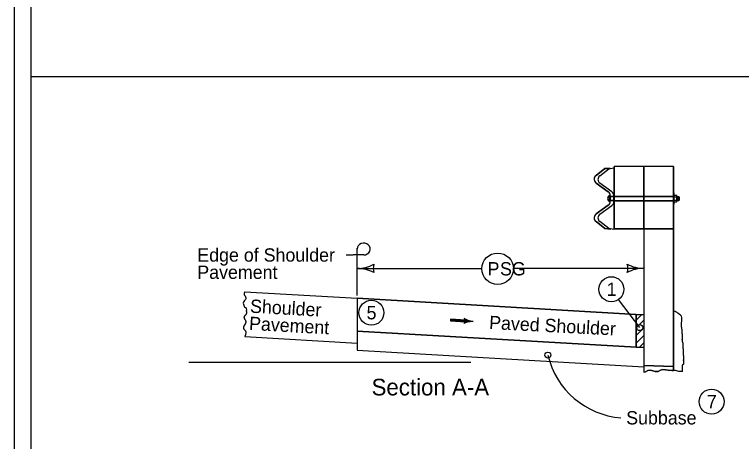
# Model space of a CAD drawing. Extents: x 10133 to 81668, y 5848 to 11018.
# Drawn here: x 10133 to 11006, y 8918 to 9431 of the extents above; entities that cross this region are included whole.
import ezdxf

# ---------------------------------------------------------------- set-up
doc = ezdxf.new("R2010")
doc.units = 0
for name, color, linetype in [('dsnStdLabel', 7, 'Continuous'), ('dsnStdLineWork', 7, 'Continuous'), ('dsnStdNote', 7, 'Continuous'), ('dsnStdShading', 7, 'Continuous'), ('Level 5', 7, 'Continuous'), ('PlanSheetShape', 7, 'Continuous'), ('SheetBorder', 7, 'Continuous'), ('SheetText', 7, 'Continuous'), ('ShtPlotShapeBatchPrint', 7, 'Continuous')]:
    doc.layers.add(name, color=color, linetype=linetype)

msp = doc.modelspace()

# ---------------------------------------------------------------- linework, layer by layer
at = {"layer": 'dsnStdLabel'}
for centre, radius in [((10849.44, 9101.26), 15), ((10561.16, 9073.08), 15), ((10883.56, 9055.15), 3.58), ((10969.88, 8966.21), 15)]:
    msp.add_circle(centre, radius, dxfattribs=at)
at = {"layer": 'dsnStdLineWork'}
for p, q in [((10846.22, 9246.01), (10852.56, 9247.12)), ((10924.05, 9248.59), (10852.96, 9248.59)), ((10852.96, 9173.94), (10852.96, 9248.59)), ((10888.5, 9173.94), (10888.5, 9248.59)), ((10924.05, 9248.59), (10924.05, 9003.55)), ((10831.02, 9237.83), (10841.78, 9246.23)), ((10835.45, 9237.6), (10846.22, 9246.01)), ((10841.78, 9246.23), (10848.11, 9246.34)), ((10845.72, 9218.29), (10831.21, 9228.71)), ((10850.19, 9218.06), (10835.63, 9228.51)), ((10847.34, 9206.19), (10847.34, 9214.27)), ((10847.34, 9212.58), (10852.77, 9212.58)), ((10848.12, 9206.85), (10848.11, 9213.66)), ((10848.29, 9212.58), (10852.96, 9212.58)), ((10852.56, 9210.04), (10852.56, 9213.44)), ((10852.96, 9212.91), (10924.05, 9212.91)), ((10852.96, 9212.58), (10924.05, 9212.58)), ((10924.05, 9216.88), (10924.73, 9216.88)), ((10924.73, 9203.55), (10924.73, 9216.88)), ((10924.73, 9214.26), (10927.7, 9214.26)), ((10924.73, 9212.24), (10927.7, 9212.24)), ((10928.06, 9207.19), (10928.06, 9213.25)), ((10928.06, 9212.55), (10930.43, 9212.55)), ((10928.95, 9212.55), (10928.95, 9207.89)), ((10929.69, 9212.55), (10929.69, 9207.89)), ((10930.43, 9212.55), (10930.88, 9212.02)), ((10930.43, 9212.55), (10930.43, 9207.89)), ((10847.34, 9207.91), (10852.96, 9207.91)), ((10848.11, 9206.85), (10848.12, 9210.26)), ((10848.12, 9210.26), (10848.12, 9206.85)), ((10852.56, 9206.63), (10852.56, 9210.04)), ((10852.56, 9210.04), (10852.56, 9206.63)), ((10852.95, 9207.58), (10924.05, 9207.58)), ((10852.96, 9207.91), (10924.05, 9207.91)), ((10924.05, 9203.55), (10924.73, 9203.55)), ((10924.73, 9208.2), (10927.7, 9208.2)), ((10924.73, 9206.18), (10927.7, 9206.18)), ((10928.06, 9207.89), (10930.43, 9207.89)), ((10930.88, 9208.42), (10930.43, 9207.89)), ((10930.88, 9212.02), (10930.88, 9208.42)), ((10831.21, 9191.8), (10845.72, 9202.22)), ((10835.63, 9191.56), (10850.19, 9202.02)), ((10841.78, 9174.29), (10831.02, 9182.68)), ((10846.22, 9174.07), (10835.45, 9182.48)), ((10848.88, 9173.6), (10841.78, 9174.29)), ((10852.56, 9172.95), (10846.22, 9174.07)), ((10888.5, 9173.94), (10852.96, 9173.94)), ((10888.5, 9173.94), (10888.5, 9001.71)), ((10408.97, 9098.32), (10544.11, 9090.46)), ((10544.11, 9090.46), (10544.11, 9036.45)), ((10544.11, 9090.46), (10879.25, 9070.97)), ((10879.25, 9064.23), (10885.99, 9070.97)), ((10879.25, 9064.23), (10885.99, 9070.97)), ((10879.25, 9064.23), (10885.99, 9070.97)), ((10879.25, 9064.23), (10885.99, 9070.97)), ((10879.25, 9070.97), (10888.49, 9070.97)), ((10879.25, 9070.97), (10879.25, 9031.55)), ((10879.25, 9055.04), (10888.49, 9064.28)), ((10879.25, 9055.04), (10888.49, 9064.28)), ((10879.25, 9055.04), (10888.49, 9064.28)), ((10879.25, 9055.04), (10888.49, 9064.28)), ((10934.1, 9064.21), (10934.1, 9064.21)), ((10879.25, 9045.82), (10888.49, 9055.05)), ((10879.25, 9045.82), (10888.49, 9055.05)), ((10879.25, 9045.82), (10888.49, 9055.05)), ((10879.25, 9045.82), (10888.49, 9055.05)), ((10879.25, 9031.55), (10544.11, 9050.86)), ((10409, 9044.31), (10544.11, 9036.45)), ((10879.25, 9036.59), (10888.49, 9045.83)), ((10544.11, 9036.45), (10544.11, 9028.03)), ((10879.25, 9031.55), (10888.49, 9031.55)), ((10883.35, 9031.55), (10888.49, 9036.68)), ((10544.11, 9028.03), (10888.5, 9008.17)), ((10342.06, 9013.62), (10680.56, 9013.62))]:
    msp.add_line(p, q, dxfattribs=at)
for points in [[(10927.76, 9212.24), (10927.83, 9212.28), (10927.91, 9212.39), (10927.99, 9212.61), (10928.05, 9212.89), (10928.05, 9210.95), (10927.99, 9211.46), (10927.94, 9211.83), (10927.82, 9212.16), (10927.76, 9212.24), (10927.82, 9212.25), (10927.92, 9212.39), (10928.01, 9212.62), (10928.03, 9212.77), (10928.03, 9211.24), (10927.96, 9211.73), (10927.9, 9211.99), (10927.8, 9212.22), (10927.83, 9212.23), (10927.97, 9212.45), (10928.01, 9212.6), (10928.01, 9211.49), (10927.82, 9212.21), (10927.99, 9212.48), (10927.99, 9211.63), (10927.85, 9212.19), (10927.97, 9212.42), (10927.98, 9211.78), (10927.87, 9212.18), (10927.96, 9212.35), (10927.96, 9211.94), (10927.89, 9212.16), (10927.94, 9212.28), (10927.94, 9212.08), (10927.91, 9212.15), (10927.92, 9212.19)], [(10928.05, 9207.51), (10928, 9207.78), (10927.96, 9207.95), (10927.87, 9208.11), (10927.75, 9208.2), (10927.83, 9208.3), (10927.91, 9208.52), (10927.97, 9208.83), (10928.05, 9209.58), (10928.05, 9207.51), (10928.03, 9207.65), (10927.99, 9207.87), (10927.91, 9208.08), (10927.79, 9208.19), (10927.83, 9208.28), (10927.89, 9208.42), (10927.99, 9208.93), (10928.03, 9209.31), (10928.03, 9207.7), (10928, 9207.82), (10927.96, 9207.98), (10927.83, 9208.19), (10927.88, 9208.36), (10927.96, 9208.69), (10928.02, 9209.02), (10928.01, 9207.86), (10927.97, 9207.98), (10927.86, 9208.18), (10927.9, 9208.39), (10927.96, 9208.65), (10927.99, 9208.82), (10927.99, 9207.96), (10927.93, 9208.07), (10927.88, 9208.18), (10927.97, 9208.64), (10927.97, 9208.04), (10927.9, 9208.18), (10927.95, 9208.47), (10927.95, 9208.12), (10927.92, 9208.19), (10927.93, 9208.29), (10927.93, 9208.21)], [(10934.57, 9040.37), (10934.51, 9040.09), (10934.51, 9039.9), (10934.51, 9039.7), (10934.51, 9039.51), (10934.51, 9039.31), (10934.51, 9039.12), (10934.51, 9038.82), (10934.51, 9038.63), (10934.61, 9038.34), (10934.71, 9038.04), (10934.9, 9037.85), (10934.9, 9037.65), (10935, 9037.46), (10935, 9037.26), (10935, 9037.06), (10935.1, 9036.97), (10935.1, 9036.77), (10935.1, 9036.58), (10935.1, 9036.38), (10935.1, 9036.19), (10935.1, 9035.99), (10935.1, 9035.7), (10935.1, 9035.4), (10935.1, 9035.21), (10935.1, 9034.92), (10935.1, 9034.72), (10935.1, 9034.52), (10935.2, 9034.43), (10935.2, 9034.23), (10935.2, 9034.04), (10935.2, 9033.84), (10935.2, 9033.65), (10935.2, 9033.45), (10935.2, 9033.25), (10935.2, 9033.06), (10935.2, 9032.86), (10935.2, 9032.67), (10935.2, 9032.47), (10935.2, 9032.28), (10935.2, 9032.08), (10935.2, 9031.89), (10935.2, 9031.69), (10935.2, 9031.5), (10935.2, 9031.3), (10935.2, 9031.1), (10935.2, 9030.91), (10935.29, 9030.81), (10935.29, 9030.62), (10935.29, 9030.42), (10935.39, 9030.32), (10935.39, 9030.13), (10935.39, 9029.93), (10935.49, 9029.83), (10935.49, 9029.64), (10935.49, 9029.44), (10935.49, 9029.25), (10935.49, 9028.96), (10935.59, 9028.66), (10935.59, 9028.47), (10935.59, 9028.27), (10935.59, 9028.08), (10935.59, 9027.88), (10935.59, 9027.69), (10935.59, 9027.49), (10935.59, 9027.29), (10935.59, 9027.1), (10935.59, 9026.9), (10935.59, 9026.71), (10935.59, 9026.51), (10935.59, 9026.32), (10935.59, 9026.12), (10935.59, 9025.93), (10935.59, 9025.73), (10935.59, 9025.54), (10935.59, 9025.34), (10935.59, 9025.14), (10935.59, 9024.95), (10935.59, 9024.75), (10935.59, 9024.56), (10935.59, 9024.36), (10935.59, 9024.17), (10935.59, 9023.97), (10935.59, 9023.78), (10935.59, 9023.58), (10935.59, 9023.39), (10935.59, 9023.19), (10935.59, 9023), (10935.68, 9022.9), (10935.68, 9022.6), (10935.68, 9022.41), (10935.78, 9022.21), (10935.88, 9021.92), (10935.88, 9021.73), (10935.98, 9021.63), (10935.98, 9021.43), (10936.07, 9021.33), (10936.17, 9021.24), (10936.17, 9021.04), (10936.17, 9020.85), (10936.17, 9020.65), (10936.27, 9020.55), (10936.27, 9020.36), (10936.27, 9020.16), (10936.27, 9019.97), (10936.27, 9019.77), (10936.27, 9019.58), (10936.27, 9019.38), (10936.27, 9019.19), (10936.27, 9018.99), (10936.27, 9018.79), (10936.27, 9018.6), (10936.27, 9018.4), (10936.27, 9018.21), (10936.27, 9018.01), (10936.27, 9017.82), (10936.27, 9017.62), (10936.27, 9017.43), (10936.27, 9017.23), (10936.27, 9017.04), (10936.27, 9016.84), (10936.27, 9016.64), (10936.27, 9016.45), (10936.27, 9016.25), (10936.27, 9016.06), (10936.27, 9015.86), (10936.27, 9015.67), (10936.27, 9015.67), (10936.27, 9015.96), (10936.27, 9016.16), (10936.27, 9016.35), (10936.27, 9016.16), (10936.27, 9015.96), (10936.27, 9015.77), (10936.27, 9015.57), (10936.27, 9015.37), (10936.27, 9015.18), (10936.27, 9014.98), (10936.27, 9014.79), (10936.27, 9014.59), (10936.27, 9014.4), (10936.27, 9014.2), (10936.27, 9014.01), (10936.27, 9013.81), (10936.27, 9013.62), (10936.27, 9013.42), (10936.17, 9013.32), (10936.17, 9013.13), (10936.17, 9012.93), (10936.17, 9012.74), (10936.17, 9012.54), (10936.17, 9012.35), (10936.17, 9012.15), (10936.17, 9011.95), (10936.17, 9011.76), (10936.17, 9011.56), (10936.17, 9011.37), (10936.07, 9011.27), (10935.98, 9011.08), (10935.88, 9010.98), (10935.78, 9010.88), (10935.68, 9010.78), (10935.49, 9010.68), (10935.29, 9010.68), (10935.2, 9010.59), (10935.1, 9010.49), (10935, 9010.39), (10934.8, 9010.29), (10934.71, 9010.2), (10934.71, 9010), (10934.61, 9009.9), (10934.61, 9009.71), (10934.61, 9009.51), (10934.61, 9009.32), (10934.61, 9002.5)], [(10934.74, 9002.5), (10930.59, 9002.38), (10926.46, 9003.55), (10921.9, 9003.55), (10917.66, 9003.97), (10911.41, 9004.71), (10908.33, 9004.08), (10905.68, 9002.28), (10901.97, 9002.49), (10896.36, 9004.08), (10893.07, 9003.55), (10890.31, 9001.96), (10888.5, 9001.71)]]:
    msp.add_lwpolyline(points, dxfattribs=at)
for centre, radius, start, end in [((10834.49, 9233.34), 5.68, 127.75002, 234.69086), ((10838.94, 9233.12), 5.68, 127.75002, 234.69086), ((10849.42, 9210.24), 4.54, 117.20289, 242.8461), ((10842.44, 9213.66), 5.68, 360, 54.69099), ((10846.88, 9213.44), 5.68, 360, 54.69099), ((10842.44, 9206.85), 5.68, 305.30901, 0), ((10846.88, 9206.63), 5.68, 305.30901, 0), ((10834.49, 9187.17), 5.68, 125.30914, 232.24998), ((10838.94, 9186.95), 5.68, 125.30914, 232.24998)]:
    msp.add_arc(centre, radius, start, end, dxfattribs=at)
for centre in [(10927.7, 9213.25), (10927.7, 9207.19)]:
    msp.add_ellipse(centre, major_axis=(0, -1.01), ratio=0.362258, start_param=6.283156, end_param=9.424748, dxfattribs=at)
for points in [[(10408.97, 9098.32), (10408.47, 9094.72), (10409.51, 9093.21), (10410.38, 9090.92), (10409.77, 9088.86), (10407.86, 9086.48), (10407.34, 9084.58), (10407.86, 9082.28), (10408.73, 9079.91), (10409.77, 9079.2), (10411.16, 9076.66), (10411.15, 9075.82)], [(10409.18, 9058.71), (10409.39, 9058.96), (10409.59, 9059.22), (10409.94, 9059.78), (10410.23, 9060.37), (10410.34, 9060.68), (10410.44, 9060.99), (10410.57, 9061.61), (10410.62, 9062.23), (10410.58, 9062.82), (10410.52, 9063.1), (10410.48, 9063.23), (10410.43, 9063.36), (10410.23, 9063.74), (10409.94, 9064.1), (10409.64, 9064.47), (10409.39, 9064.86), (10409.25, 9065.15), (10409.12, 9065.43), (10408.86, 9066.01), (10408.65, 9066.57), (10408.58, 9066.86), (10408.53, 9067.16), (10408.52, 9067.29), (10408.52, 9067.42), (10408.67, 9068.19), (10408.88, 9068.71), (10409.13, 9069.22), (10409.58, 9069.86), (10410.1, 9070.4), (10410.61, 9070.95), (10410.84, 9071.26), (10411.04, 9071.6), (10411.25, 9072.07), (10411.4, 9072.54), (10411.51, 9073.02), (10411.54, 9073.26), (10411.55, 9073.38), (10411.56, 9073.5), (10411.51, 9074.01), (10411.36, 9074.52), (10411.31, 9074.65), (10411.26, 9074.77), (10411.21, 9074.9), (10411.18, 9075.03), (10411.15, 9075.82)], [(10934.57, 9040.37), (10934.89, 9043.27), (10934.67, 9048.14), (10934.23, 9053.89), (10933.56, 9058.31), (10933.78, 9061.62), (10934.23, 9065.83), (10933.56, 9068.92), (10931.35, 9070.91), (10929.36, 9072.68), (10927.15, 9073.79), (10924.94, 9075.11), (10924.06, 9075.78)], [(10409.18, 9058.71), (10408.97, 9058.47), (10408.72, 9058.24), (10408.49, 9058), (10408.3, 9057.73), (10408.16, 9057.45), (10408.02, 9057.16), (10407.76, 9056.59), (10407.65, 9056.31), (10407.56, 9056.02), (10407.49, 9055.73), (10407.46, 9055.58), (10407.44, 9055.43), (10407.45, 9054.92), (10407.58, 9054.4), (10407.79, 9053.88), (10408.04, 9053.37), (10408.49, 9052.74), (10409.01, 9052.19), (10409.52, 9051.64), (10409.75, 9051.34), (10409.95, 9051), (10410.35, 9050.05), (10410.46, 9049.58), (10410.47, 9049.1), (10410.43, 9048.81), (10410.39, 9048.52), (10410.33, 9048.23), (10410.26, 9047.95), (10409.95, 9046.8), (10409.77, 9046.19), (10409.58, 9045.59), (10409.35, 9045), (10409.22, 9044.71), (10409.08, 9044.42), (10409, 9044.31)]]:
    msp.add_spline(points, degree=3, dxfattribs=at)
at = {"layer": 'dsnStdNote'}
msp.add_circle((10773.25, 9022.18), 3.54, dxfattribs=at)
msp.add_circle((10773.25, 9022.18), 3.54, dxfattribs=at)
at = {"layer": 'dsnStdShading'}
for p, q in [((12307.76, 9356.36), (10152.18, 9356.36)), ((10883.56, 9055.15), (10858.18, 9089.07))]:
    msp.add_line(p, q, dxfattribs=at)
at = {"layer": 'Level 5'}
msp.add_circle((10561.16, 9073.08), 15, dxfattribs=at)
at = {"layer": 'PlanSheetShape'}
for p, q in [((10831.21, 9228.71), (10845.72, 9218.29)), ((10845.72, 9202.22), (10831.21, 9191.8)), ((10879.25, 9070.97), (10544.11, 9090.46)), ((10544.11, 9090.46), (10544.11, 9050.86)), ((10879.25, 9031.55), (10879.25, 9070.97)), ((10544.11, 9050.86), (10879.25, 9031.55))]:
    msp.add_line(p, q, dxfattribs=at)
for points in [[(10888.5, 9212.91), (10888.5, 9248.59), (10852.96, 9248.59), (10852.96, 9212.91), (10852.96, 9212.91), (10888.5, 9212.91)], [(10924.05, 9212.91), (10924.05, 9216.91), (10924.05, 9248.59), (10888.5, 9248.59), (10888.5, 9212.91), (10924.05, 9212.91)], [(10835.46, 9237.61), (10835.45, 9237.6), (10846.22, 9246.01), (10848.11, 9246.34), (10841.78, 9246.23), (10831.02, 9237.83)], [(10850.16, 9218.07), (10850.19, 9218.06), (10835.63, 9228.51), (10835.66, 9228.49)], [(10848.11, 9213.66), (10848.11, 9212.58), (10852.56, 9212.58), (10852.56, 9213.44), (10852.56, 9213.44)], [(10852.96, 9212.58), (10852.96, 9207.91), (10852.96, 9207.91), (10888.5, 9207.91), (10888.5, 9212.58), (10852.96, 9212.58), (10852.96, 9212.58)], [(10924.05, 9207.91), (10924.05, 9212.58), (10888.5, 9212.58), (10888.5, 9207.91), (10924.05, 9207.91)], [(10852.56, 9206.63), (10852.56, 9206.63), (10852.56, 9207.91), (10848.12, 9207.91), (10848.12, 9206.85), (10848.12, 9207.91), (10848.11, 9207.91), (10848.11, 9206.85)], [(10852.96, 9207.58), (10852.96, 9173.94), (10888.5, 9173.94), (10888.5, 9207.58), (10852.96, 9207.58)], [(10924.05, 9173.94), (10924.05, 9203.58), (10924.05, 9207.58), (10888.5, 9207.58), (10888.5, 9173.94), (10924.05, 9173.94)], [(10835.66, 9191.58), (10835.63, 9191.56), (10850.19, 9202.02), (10850.16, 9202)], [(10831.02, 9182.68), (10841.78, 9174.29), (10848.88, 9173.6), (10846.22, 9174.07), (10835.45, 9182.48), (10835.46, 9182.46)], [(10924.05, 9008.6), (10924.05, 9173.94), (10888.5, 9173.94), (10888.5, 9070.97), (10888.5, 9064.28), (10888.5, 9064.28), (10888.5, 9064.28), (10888.5, 9055.05), (10888.5, 9055.05), (10888.5, 9055.05), (10888.5, 9045.91), (10888.5, 9045.91), (10888.5, 9045.91), (10888.5, 9038.98), (10888.5, 9009.76), (10924.05, 9008.6)], [(10924.05, 9008.6), (10888.5, 9009.76), (10888.5, 9001.71), (10890.31, 9001.96), (10893.07, 9003.55), (10896.36, 9004.08), (10901.97, 9002.49), (10905.68, 9002.28), (10908.33, 9004.08), (10911.41, 9004.71), (10917.66, 9003.97), (10921.9, 9003.55), (10924.05, 9003.55), (10924.05, 9008.6)]]:
    msp.add_lwpolyline(points, dxfattribs=at)
msp.add_lwpolyline([(10852.56, 9212.58), (10848.11, 9212.58), (10848.11, 9209.12), (10848.12, 9210.26), (10848.12, 9207.91), (10852.56, 9207.91)], close=True, dxfattribs=at)
for centre, start, end in [((10834.49, 9233.34), 127.75002, 234.69086), ((10838.94, 9233.12), 127.75002, 234.69086), ((10842.44, 9213.66), 0, 54.69099), ((10846.88, 9213.44), 0, 54.69099), ((10842.44, 9206.85), 305.30901, 0), ((10846.88, 9206.63), 305.30901, 0), ((10834.49, 9187.17), 125.30914, 232.24998), ((10838.94, 9186.95), 125.30914, 232.24998)]:
    msp.add_arc(centre, 5.68, start, end, dxfattribs=at)
at = {"layer": 'SheetBorder'}
msp.add_lwpolyline([(10132.52, 9944.02), (13267.53, 9944.02), (13267.53, 7924.02), (10132.52, 7924.02)], close=True, dxfattribs=at)
at = {"layer": 'SheetText'}
for p, q in [((10530.74, 9142.39), (10539.43, 9142.39)), ((10551.92, 9142.39), (10539.43, 9142.39)), ((10544.11, 9129.54), (10544.11, 9150.4)), ((10544.11, 9093.61), (10544.11, 9129.54)), ((10544.11, 9126.22), (10693.94, 9126.22)), ((10731.8, 9126.38), (10888.5, 9126.38)), ((10674.32, 9063.12), (10656.11, 9064.17)), ((10674.33, 9064.12), (10674.33, 9064.12)), ((10674.21, 9062.18), (10674.21, 9062.18))]:
    msp.add_line(p, q, dxfattribs=at)
for points in [[(10674.34, 9064.06), (10656.18, 9065.11), (10656.05, 9063.23), (10674.21, 9062.18), (10674.27, 9063.79), (10656.4, 9064.88), (10656.34, 9063.39), (10673.83, 9062.44), (10673.95, 9063.56), (10656.63, 9064.62), (10656.61, 9063.62), (10673.62, 9062.64), (10673.71, 9063.34), (10656.82, 9064.4), (10656.8, 9063.84), (10673.41, 9062.9)], [(10673.94, 9065.31), (10674.63, 9064.15), (10674.61, 9062.5), (10673.85, 9061.1), (10676.61, 9061.97), (10679.8, 9062.62), (10680.7, 9062.75), (10678.46, 9063.3), (10675.23, 9064.53), (10674.29, 9065.06), (10674.41, 9061.55), (10679.36, 9062.77), (10674.72, 9064.35), (10674.73, 9061.93), (10678.13, 9062.86), (10675.13, 9063.72), (10674.9, 9062.34), (10677.06, 9062.84), (10675.47, 9063.35), (10675.33, 9062.69), (10676.12, 9062.85)]]:
    msp.add_lwpolyline(points, dxfattribs=at)
msp.add_circle((10712.87, 9125.82), 18.93, dxfattribs=at)
for centre, radius, start, end in [((10544.11, 9168.72), 42.5, 270, 298.07249), ((10544.11, 9083.72), 42.5, 61.92751, 90), ((10579.75, 9126.22), 16.42, 162.26665, 197.73335), ((10852.87, 9126.38), 16.42, 342.26665, 17.73335), ((10888.5, 9168.88), 42.5, 241.92751, 270), ((10888.5, 9083.88), 42.5, 90, 118.07249), ((10868.48, 9044.3), 97.76, 193.07698, 265.55799)]:
    msp.add_arc(centre, radius, start, end, dxfattribs=at)
for centre, major_axis, start_param, end_param in [((10551.92, 9149.53), (-7.81, 0), 1.570796, 6.283185), ((10670.55, 9063.33), (3.88, 0), 5.202895, 7.237436), ((10685.61, 9082.75), (-22.17, 0), 0.954258, 1.478381), ((10682.82, 9042.33), (22.17, 0), 1.537172, 2.061295)]:
    msp.add_ellipse(centre, major_axis=major_axis, ratio=0.913811, start_param=start_param, end_param=end_param, dxfattribs=at)
at = {"layer": 'ShtPlotShapeBatchPrint'}
msp.add_line((10152.18, 9924.36), (10152.18, 8314.36), dxfattribs=at)

# ---------------------------------------------------------------- texts
at = {"layer": 'dsnStdLabel'}
for s, p in [('1', (10843.82, 9093.26)), ('5', (10555.39, 9065.08)), ('7', (10964.18, 8958.21))]:
    msp.add_text(s, height=16, dxfattribs=at).set_placement(p)
at = {"layer": 'SheetText'}
for s, height, p in [('Edge of Shoulder ', 16, (10352.05, 9134.39)), ('P', 16, (10700.74, 9117.82)), ('SG', 16, (10715.66, 9117.82)), ('Pavement', 16, (10352.05, 9113.68)), ('Section A-A', 20, (10561.37, 8973.69)), ('Subbase', 16, (10867.26, 8938.83))]:
    msp.add_text(s, height=height, dxfattribs=at).set_placement(p)
for s, rotation, p in [('Shoulder', 356.73462, (10415.1, 9073.15)), ('Pavement', 356.73462, (10413.92, 9052.48)), ('Paved Shoulder ', 357.0678, (10702.33, 9053.48))]:
    msp.add_text(s, height=16, rotation=rotation, dxfattribs=at).set_placement(p)

doc.saveas('drawing.dxf')
